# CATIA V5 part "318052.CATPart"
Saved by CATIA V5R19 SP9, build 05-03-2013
Part number: 318052
Source: Unknown
Bounding box of the stored display mesh (mm): x 133 to 250, y 104 to 107, z 509.556 to 594
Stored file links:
  D:\16-SIL\kale oto\R19_V2\318052.CATPart
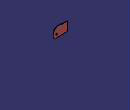
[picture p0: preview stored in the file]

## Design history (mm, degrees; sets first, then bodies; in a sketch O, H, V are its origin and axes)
Body1 "157\\123\\MANIFOLD_SOLID_BREP #73462" (main body)
  Solid1: solid without history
